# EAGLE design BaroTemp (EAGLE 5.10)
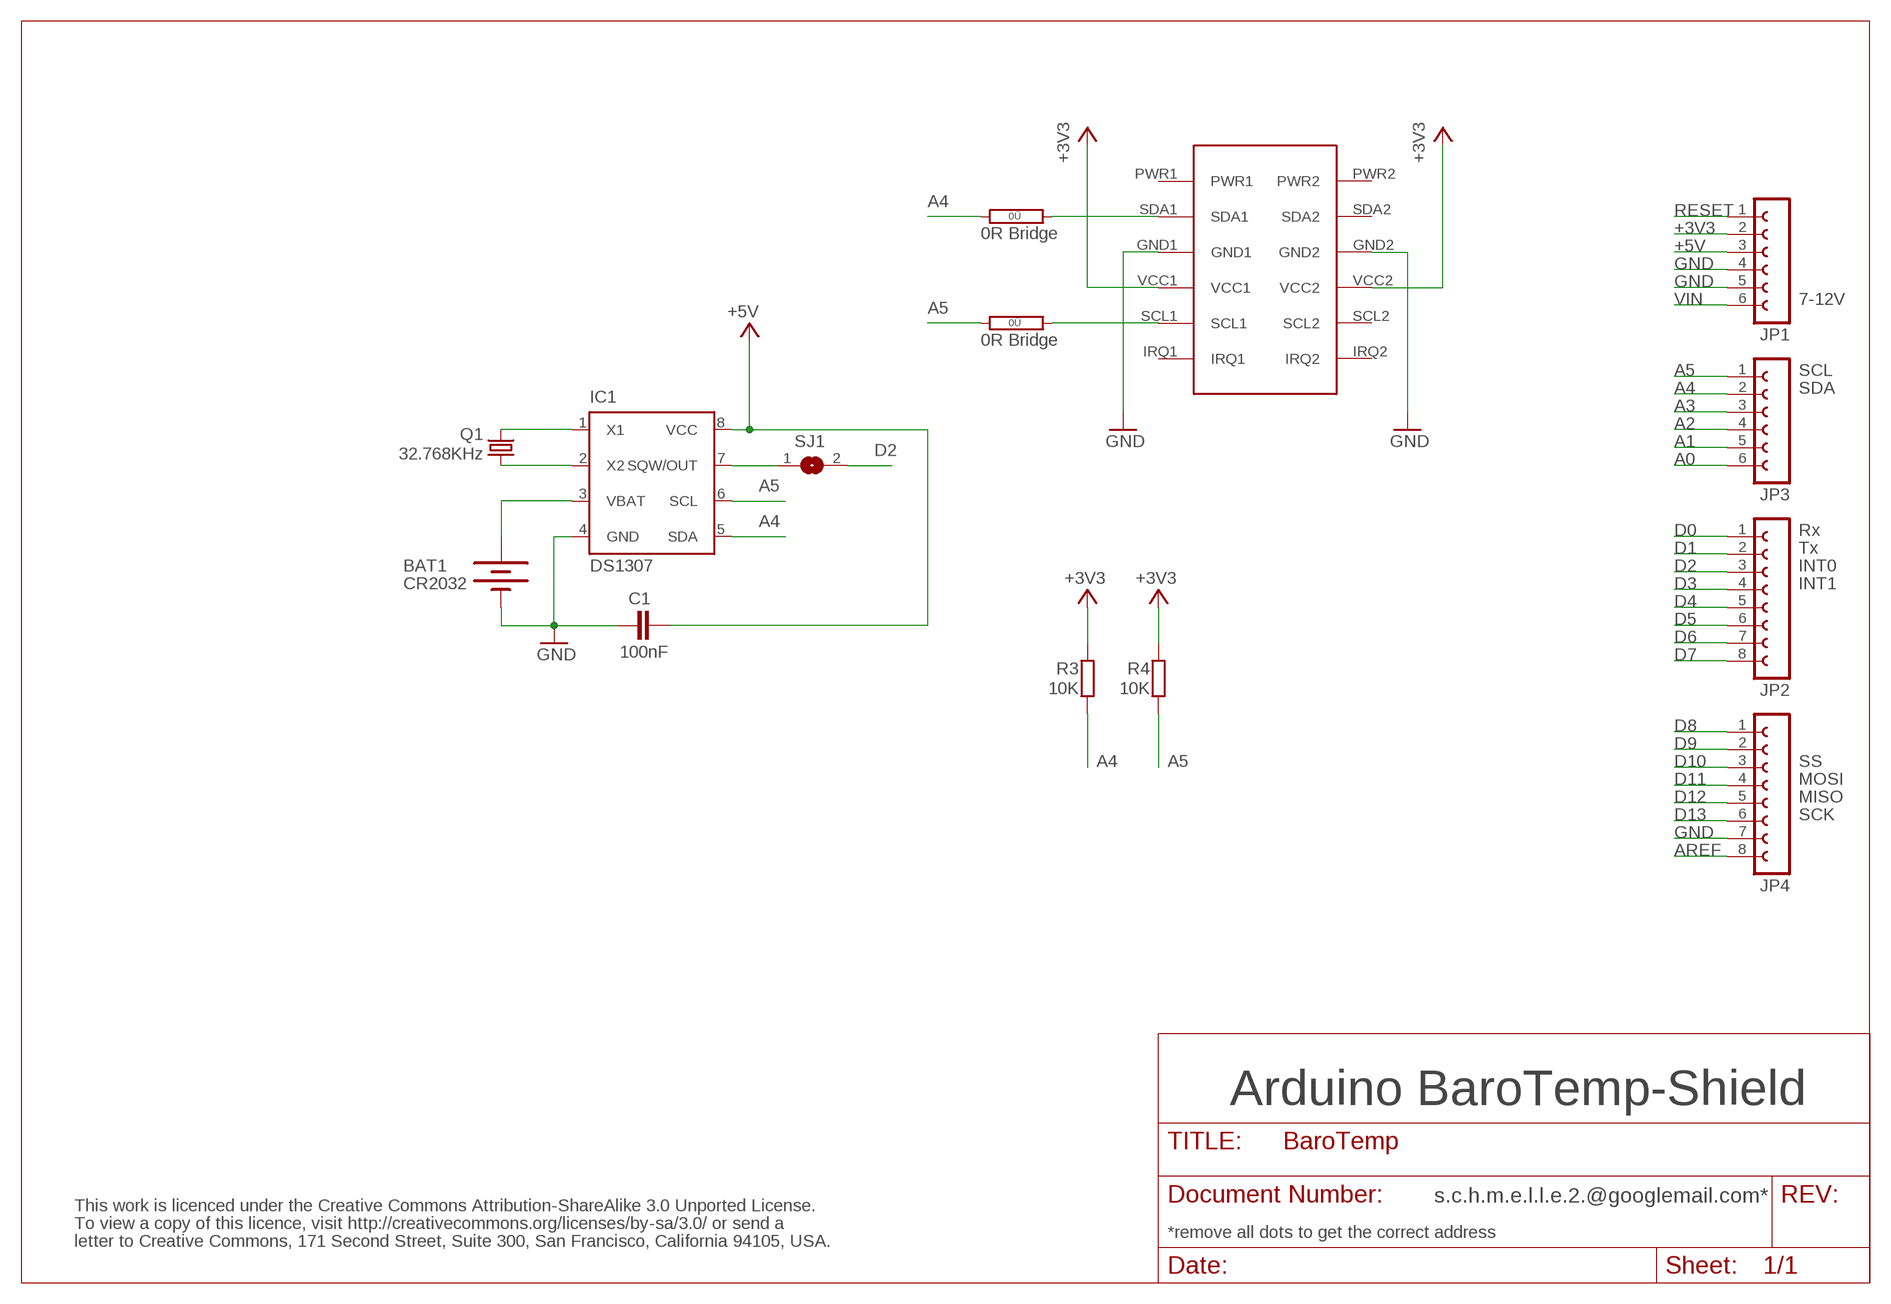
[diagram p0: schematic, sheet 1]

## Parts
BAT1  CR2032  BATTERY20PTH  [BATTCOM_20MM_PTH]
C1  100nF  C-EU050-025X075  [C050-025X075]
IC1  DS1307  [DIL08]
JP1  FE06-1  [FE06]
JP2  FE08-1  [FE08]
JP3  FE06-1  [FE06]
JP4  FE08-1  [FE08]
Q1  32.768KHz  CRYSTALTC26V  [TC26V]
R1  0R Bridge  0R  [0R/10]
R2  0R Bridge  0R  [0R/10]
R3  10K  R-EU_0207/10  [0207/10]
R4  10K  R-EU_0207/10  [0207/10]
SJ1  SJ  [SJ]
U$1  PRESSURE_PLUG  [BMP085-BO]

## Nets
+3V3: JP1.2 R3.2 R4.2 U$1.VCC1 U$1.VCC2
+5V: C1.2 IC1.8(VCC) JP1.3
A0: JP3.6
A1: JP3.5
A2: JP3.4
A3: JP3.3
A4: IC1.5(SDA) JP3.2 R1.1 R3.1
A5: IC1.6(SCL) JP3.1 R2.1 R4.1
AREF: JP4.8
D0: JP2.1
D1: JP2.2
D2: JP2.3 SJ1.2
D3: JP2.4
D4: JP2.5
D5: JP2.6
D6: JP2.7
D7: JP2.8
D8: JP4.1
D9: JP4.2
D10: JP4.3
D11: JP4.4
D12: JP4.5
D13: JP4.6
GND: BAT1.2(-) C1.1 IC1.4(GND) JP1.4 JP1.5 JP4.7 U$1.GND1 U$1.GND2
N$1: BAT1.1(+) IC1.3(VBAT)
N$2: R2.2 U$1.SCL1
N$4: IC1.1(X1) Q1.2
N$5: R1.2 U$1.SDA1
N$6: IC1.2(X2) Q1.1
N$285: IC1.7(SQW/OUT) SJ1.1
RESET: JP1.1
VIN: JP1.6
Unconnected: U$1.IRQ1 U$1.IRQ2 U$1.SCL2 U$1.SDA2

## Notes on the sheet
- 7-12V
- SCL
- SDA
- Rx
- Tx
- INT0
- INT1
- SS
- MOSI
- MISO
- SCK
- Arduino BaroTemp-Shield
- s.c.h.m.e.l.l.e.2.@googlemail.com*
- This work is licenced under the Creative Commons Attribution-ShareAlike 3.0 Unported License.
- To view a copy of this licence, visit http://creativecommons.org/licenses/by-sa/3.0/ or send a
- *remove all dots to get the correct address
- letter to Creative Commons, 171 Second Street, Suite 300, San Francisco, California 94105, USA.

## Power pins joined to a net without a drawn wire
PWR1: U$1.PWR1
PWR2: U$1.PWR2

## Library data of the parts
BAT1 = SparkFun:BATTERY: Battery Holders
C1 = resistor:C-EU: CAPACITOR, European symbol
IC1 = Peter-Privat:DS1307: I2C Serial RTC w/56 bytes battery backed RAM
JP1 JP3 = con-lsta:FE06-1: FEMALE HEADER
JP2 JP4 = con-lsta:FE08-1: FEMALE HEADER
Q1 = crystal:CRYSTAL: CRYSTAL
R1 R2 = jumper:0R: Bridge 0R 10mm
R3 R4 = resistor:R-EU_: RESISTOR, European symbol
SJ1 = jumper:SJ: SMD solder JUMPER
U$1 = Peter-Privat:PRESSURE_PLUG: BMP085 Breakout Board von http://shop.jeelabs.com/products/pressure-plug

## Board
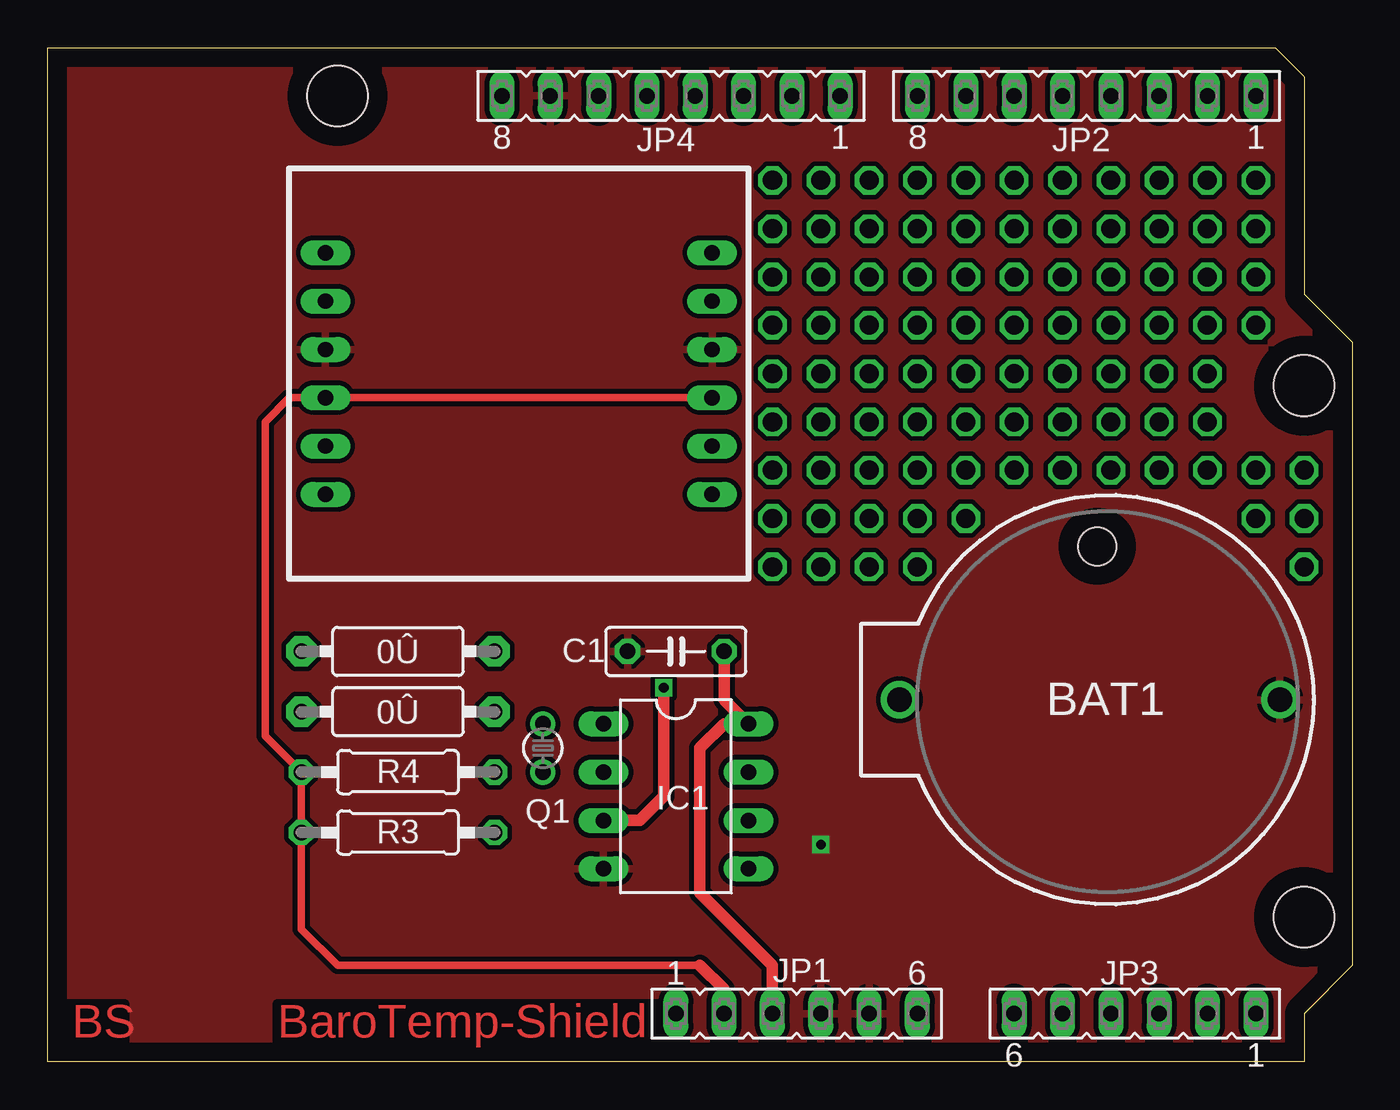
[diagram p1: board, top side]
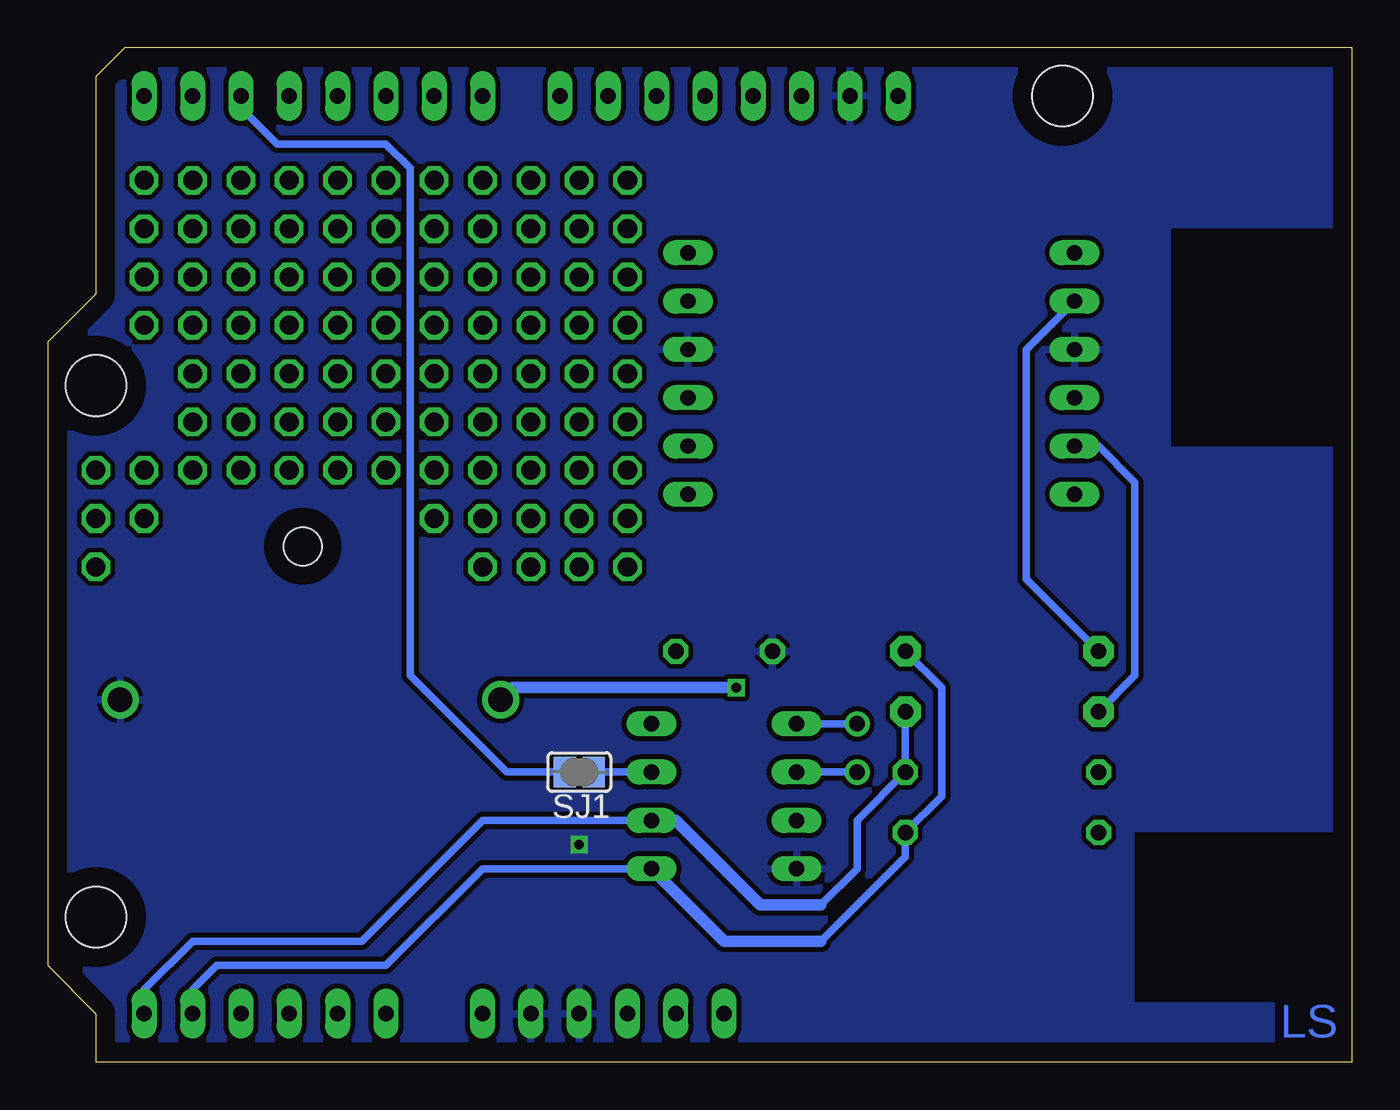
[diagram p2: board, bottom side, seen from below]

Size 68.58 x 53.34 mm. Coordinates in mm from the lower left corner, seen from the top.
Outline: 0,0 0,53.34 64.52,53.34 66.04,51.82 66.04,40.39 68.58,37.85 68.58,5.08 66.04,2.54 66.04,0 0,0
Copper layers (1*16): Top 0.035mm / dielectric 1.5mm / Bottom 0.035mm
Design rules "Bilex DRU *": minimum track width 10mil, minimum drill 24mil, track to track 10mil, track to pad 10mil, pad to pad 10mil, via to via 10mil, smd to smd 10mil, copper to edge 40mil, drill to drill 8mil, minimum pad ring 10mil, minimum via ring 8mil, stop-mask expansion 4mil, vias tented up to drill 0mil, thermal gap 10mil
Holes 3.2 mm at 15.24,50.8 66.04,35.56 66.04,7.62
Holes 2 mm at 55.17,27.11
tKeepout: area 0,32.4 to 9.5,43.8; area 0,3.2 to 11.4,12.1
bKeepout: area 0,32.4 to 9.5,43.8; area 0,32.4 to 9.5,43.8; area 0,3.2 to 11.4,12.1
bRestrict: area 0,32.4 to 9.5,43.8; area 0,32.4 to 9.5,43.8; area 0,3.2 to 11.4,12.1

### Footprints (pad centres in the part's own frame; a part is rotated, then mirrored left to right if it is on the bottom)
BATTCOM_20MM_PTH = drill 1.3 round: 1 20,0; 2 0,0
C050-025X075 = drill 0.813 octagon: 1 -2.54,0; 2 2.54,0
DIL08 = drill 0.813 long: 1 -3.81,-3.81; 2 -1.27,-3.81; 3 1.27,-3.81; 4 3.81,-3.81; 5 3.81,3.81; 6 1.27,3.81; 7 -1.27,3.81; 8 -3.81,3.81
FE06 = drill 0.813 long: 1 -6.35,0; 2 -3.81,0; 3 -1.27,0; 4 1.27,0; 5 3.81,0; 6 6.35,0
FE08 = drill 0.813 long: 1 -8.89,0; 2 -6.35,0; 3 -3.81,0; 4 -1.27,0; 5 1.27,0; 6 3.81,0; 7 6.35,0; 8 8.89,0
TC26V = drill 0.813 round: 1 -1.27,0; 2 1.27,0
0R/10 = drill 0.813 pad 1.6 octagon: 1 -5.08,0; 2 5.08,0
0207/10 = drill 0.813 octagon: 1 -5.08,0; 2 5.08,0
SJ = smd 1.168 x 1.6: 1 -0.762,0; 2 0.762,0
BMP085-BO = drill 0.8 long: GND1 -10.16,1.27; GND2 10.16,1.27; IRQ1 -10.16,-6.35; IRQ2 10.16,-6.35; PWR1 -10.16,6.35; PWR2 10.16,6.35; SCL1 -10.16,-3.81; SCL2 10.16,-3.81; SDA1 -10.16,3.81; SDA2 10.16,3.81; VCC1 -10.16,-1.27; VCC2 10.16,-1.27

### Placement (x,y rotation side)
BAT1  64.77,19.05 180 top
C1  33.02,21.59 0 top
IC1  33.02,13.97 270 top
JP1  39.37,2.54 0 top
JP2  54.61,50.8 180 top
JP3  57.15,2.54 180 top
JP4  32.77,50.8 180 top
Q1  26.04,16.51 90 top
R1  18.41,21.59 180 top
R2  18.41,18.41 180 top
R3  18.41,12.06 180 top
R4  18.41,15.24 180 top
SJ1  40.64,15.24 180 bottom
U$1  24.77,36.2 0 top

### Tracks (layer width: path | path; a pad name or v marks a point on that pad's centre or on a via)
+3V3
  Top 0.406: 34.29,5.08 15.24,5.08 13.34,6.99 R3.2 R4.2 11.43,17.14 11.43,33.66 12.7,34.92 U$1.VCC1 U$1.VCC2
  Top 0.61: JP1.2 35.56,3.81 34.29,5.08
+5V
  Top 0.61: C1.2 35.56,19.05 IC1.8 35.56,17.78 34.29,16.51 34.29,8.89 38.1,5.08 JP1.3
A4
  Bottom 0.406: JP3.2 60.96,3.81 59.69,5.08 50.8,5.08 45.72,10.16 IC1.5 | 27.94,6.35 23.5,10.79 R3.1 21.59,13.97 21.59,19.68 R1.1
  Bottom 0.61: IC1.5 33.02,6.35 27.94,6.35
A5
  Bottom 0.406: JP3.1 63.5,3.81 60.96,6.35 52.07,6.35 45.72,12.7 IC1.6 | 27.94,8.26 26.04,10.16 26.04,12.7 R4.1 R2.1
  Bottom 0.61: 27.94,8.26 31.11,8.26 35.56,12.7 IC1.6
D2
  Bottom 0.406: SJ1.2 44.45,15.24 49.53,20.32 49.53,46.99 50.8,48.26 56.52,48.26 58.42,50.16 JP2.3
GND  (via drill 0.5)
  other vias: 40.64,11.43
  pour Top: 0,0 0,53.34 64.52,53.34 66.04,51.82 66.04,40.39 68.58,37.85 68.58,5.08 66.04,2.54 66.04,0
  pour Bottom: 0,0 0,53.34 64.52,53.34 66.04,51.82 66.04,40.39 68.58,37.85 68.58,5.08 66.04,2.54 66.04,0
N$1  (via drill 0.5)
  Top 0.61: v32.38,19.68 32.38,13.97 31.11,12.7 IC1.3
  Bottom 0.61: BAT1.1 44.13,19.68 v32.38,19.68
N$2
  Bottom 0.406: U$1.SCL1 13.34,32.38 11.43,30.48 11.43,20.32 R2.2
N$3  (via drill 1 pad 1.42)
  other vias: 40.64,46.35
N$4
  Bottom 0.406: Q1.2 IC1.1
N$5
  Bottom 0.406: R1.2 17.14,25.4 17.14,37.47 U$1.SDA1
N$6
  Bottom 0.406: Q1.1 IC1.2
N$7  (via drill 1 pad 1.42)
  other vias: 40.64,43.81
N$8  (via drill 1 pad 1.42)
  other vias: 40.64,41.27
N$9  (via drill 1 pad 1.42)
  other vias: 40.64,38.73
N$10  (via drill 1 pad 1.42)
  other vias: 40.64,36.2
N$11  (via drill 1 pad 1.42)
  other vias: 40.64,33.66
N$12  (via drill 1 pad 1.42)
  other vias: 40.64,31.11
N$13  (via drill 1 pad 1.42)
  other vias: 40.64,28.57
N$14  (via drill 1 pad 1.42)
  other vias: 40.64,26.04
N$15  (via drill 1 pad 1.42)
  other vias: 38.1,26.04
N$16  (via drill 1 pad 1.42)
  other vias: 38.1,28.57
N$17  (via drill 1 pad 1.42)
  other vias: 38.1,31.11
N$18  (via drill 1 pad 1.42)
  other vias: 38.1,33.66
N$19  (via drill 1 pad 1.42)
  other vias: 38.1,36.2
N$20  (via drill 1 pad 1.42)
  other vias: 38.1,38.73
N$21  (via drill 1 pad 1.42)
  other vias: 38.1,41.27
N$22  (via drill 1 pad 1.42)
  other vias: 38.1,43.81
N$23  (via drill 1 pad 1.42)
  other vias: 38.1,46.35
N$55  (via drill 1 pad 1.42)
  other vias: 43.18,46.35
N$56  (via drill 1 pad 1.42)
  other vias: 43.18,43.81
N$57  (via drill 1 pad 1.42)
  other vias: 43.18,41.27
N$58  (via drill 1 pad 1.42)
  other vias: 43.18,38.73
N$59  (via drill 1 pad 1.42)
  other vias: 43.18,36.2
N$60  (via drill 1 pad 1.42)
  other vias: 43.18,33.66
N$61  (via drill 1 pad 1.42)
  other vias: 43.18,31.11
N$64  (via drill 1 pad 1.42)
  other vias: 45.72,31.11
N$65  (via drill 1 pad 1.42)
  other vias: 45.72,33.66
N$66  (via drill 1 pad 1.42)
  other vias: 45.72,36.2
N$67  (via drill 1 pad 1.42)
  other vias: 45.72,38.73
N$68  (via drill 1 pad 1.42)
  other vias: 45.72,41.27
N$69  (via drill 1 pad 1.42)
  other vias: 45.72,43.81
N$70  (via drill 1 pad 1.42)
  other vias: 45.72,46.35
N$71  (via drill 1 pad 1.42)
  other vias: 48.26,46.35
N$72  (via drill 1 pad 1.42)
  other vias: 48.26,43.81
N$73  (via drill 1 pad 1.42)
  other vias: 48.26,41.27
N$74  (via drill 1 pad 1.42)
  other vias: 48.26,38.73
N$75  (via drill 1 pad 1.42)
  other vias: 48.26,36.2
N$76  (via drill 1 pad 1.42)
  other vias: 48.26,33.66
N$77  (via drill 1 pad 1.42)
  other vias: 48.26,31.11
N$78  (via drill 1 pad 1.42)
  other vias: 48.26,28.57
N$79  (via drill 1 pad 1.42)
  other vias: 50.8,31.11
N$80  (via drill 1 pad 1.42)
  other vias: 50.8,33.66
N$81  (via drill 1 pad 1.42)
  other vias: 50.8,36.2
N$82  (via drill 1 pad 1.42)
  other vias: 50.8,38.73
N$83  (via drill 1 pad 1.42)
  other vias: 50.8,41.27
N$84  (via drill 1 pad 1.42)
  other vias: 50.8,43.81
N$85  (via drill 1 pad 1.42)
  other vias: 50.8,46.35
N$86  (via drill 1 pad 1.42)
  other vias: 53.34,46.35
N$87  (via drill 1 pad 1.42)
  other vias: 53.34,43.81
N$88  (via drill 1 pad 1.42)
  other vias: 53.34,41.27
N$89  (via drill 1 pad 1.42)
  other vias: 53.34,38.73
N$90  (via drill 1 pad 1.42)
  other vias: 53.34,36.2
N$91  (via drill 1 pad 1.42)
  other vias: 53.34,33.66
N$92  (via drill 1 pad 1.42)
  other vias: 53.34,31.11
N$93  (via drill 1 pad 1.42)
  other vias: 55.88,31.11
N$94  (via drill 1 pad 1.42)
  other vias: 55.88,33.66
N$95  (via drill 1 pad 1.42)
  other vias: 55.88,36.2
N$96  (via drill 1 pad 1.42)
  other vias: 55.88,38.73
N$97  (via drill 1 pad 1.42)
  other vias: 55.88,41.27
N$98  (via drill 1 pad 1.42)
  other vias: 55.88,43.81
N$99  (via drill 1 pad 1.42)
  other vias: 55.88,46.35
N$100  (via drill 1 pad 1.42)
  other vias: 58.42,46.35
N$101  (via drill 1 pad 1.42)
  other vias: 58.42,43.81
N$102  (via drill 1 pad 1.42)
  other vias: 58.42,41.27
N$103  (via drill 1 pad 1.42)
  other vias: 58.42,38.73
N$104  (via drill 1 pad 1.42)
  other vias: 58.42,36.2
N$105  (via drill 1 pad 1.42)
  other vias: 58.42,33.66
N$106  (via drill 1 pad 1.42)
  other vias: 58.42,31.11
N$107  (via drill 1 pad 1.42)
  other vias: 60.96,31.11
N$108  (via drill 1 pad 1.42)
  other vias: 60.96,33.66
N$109  (via drill 1 pad 1.42)
  other vias: 60.96,36.2
N$110  (via drill 1 pad 1.42)
  other vias: 60.96,38.73
N$111  (via drill 1 pad 1.42)
  other vias: 60.96,41.27
N$112  (via drill 1 pad 1.42)
  other vias: 60.96,43.81
N$113  (via drill 1 pad 1.42)
  other vias: 60.96,46.35
N$114  (via drill 1 pad 1.42)
  other vias: 63.5,46.35
N$115  (via drill 1 pad 1.42)
  other vias: 63.5,43.81
N$116  (via drill 1 pad 1.42)
  other vias: 63.5,41.27
N$117  (via drill 1 pad 1.42)
  other vias: 63.5,38.73
N$118  (via drill 1 pad 1.42)
  other vias: 63.5,31.11
N$119  (via drill 1 pad 1.42)
  other vias: 63.5,28.57
N$120  (via drill 1 pad 1.42)
  other vias: 66.04,31.11
N$121  (via drill 1 pad 1.42)
  other vias: 66.04,28.57
N$122  (via drill 1 pad 1.42)
  other vias: 66.04,26.04
N$134  (via drill 1)
  other vias: 43.18,26.04
N$135  (via drill 1)
  other vias: 45.72,26.04
N$136  (via drill 1)
  other vias: 45.72,28.57
N$137  (via drill 1)
  other vias: 43.18,28.57
N$285
  Bottom 0.406: IC1.7 SJ1.1

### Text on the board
Top: BS | BaroTemp-Shield
Bottom: LS
Document: This work is licenced under the Creative Commons Attribution-ShareAlike 3.0 Unported License. | To view a copy of this licence, visit http://creativecommons.org/licenses/by-sa/3.0/ or send a | letter to Creative Commons, 171 Second Street, Suite 300, San Francisco, California 94105, USA.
